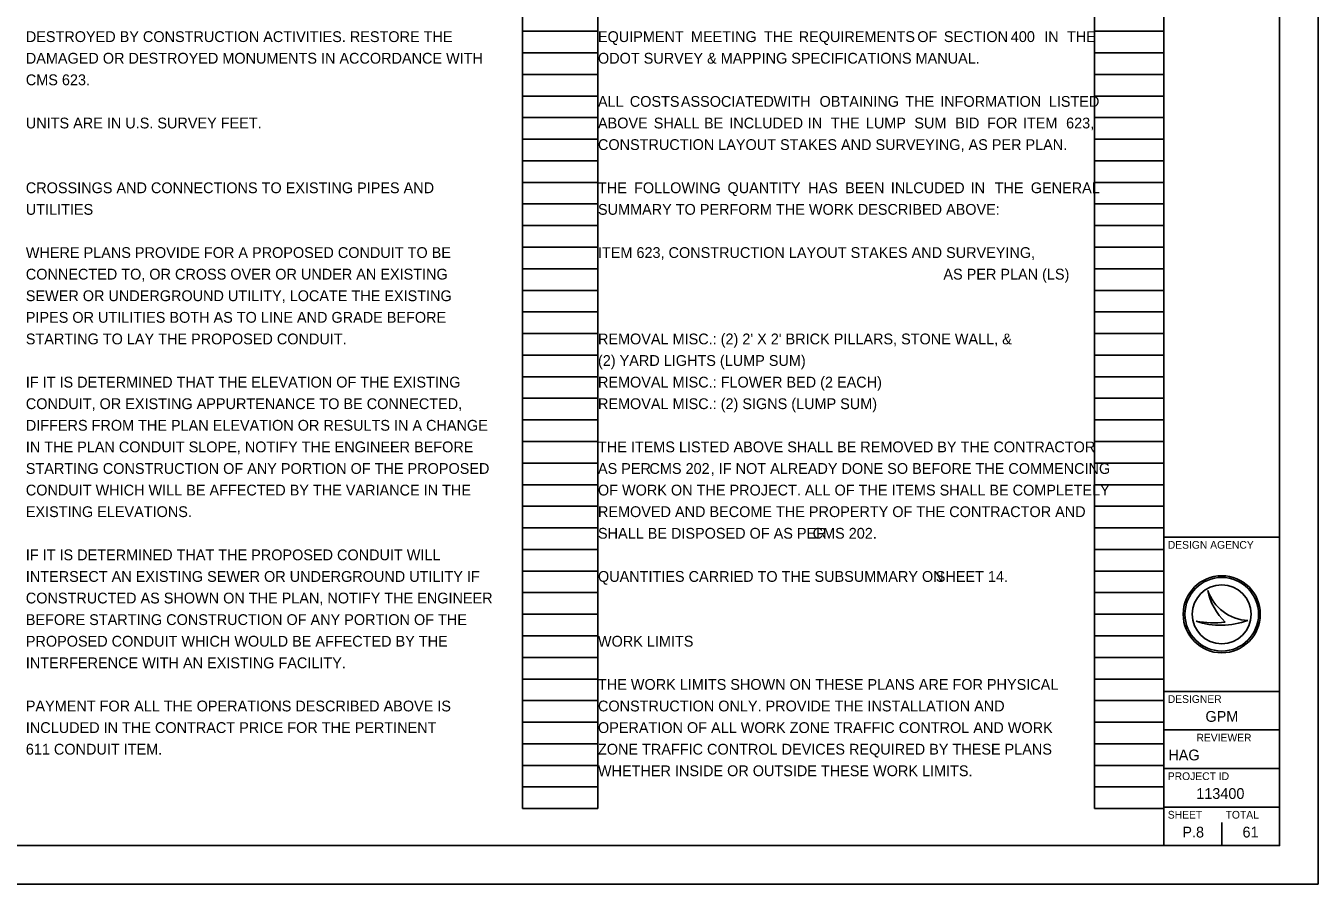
# Model space of a CAD drawing. Extents: x 0 to 34, y 0 to 22.
# Drawn here: x 17.24 to 34, y 0 to 11.13 of the extents above; entities that cross this region are included whole.
import ezdxf

# ---------------------------------------------------------------- set-up
doc = ezdxf.new("R2010")
doc.units = 0
for name, color, linetype in [('SH_Border', 7, 'Continuous'), ('SH_Cut_Line', 7, 'Continuous'), ('SH_Data', 7, 'Continuous'), ('SH_Text', 7, 'Continuous')]:
    doc.layers.add(name, color=color, linetype=linetype)

msp = doc.modelspace()

# ---------------------------------------------------------------- linework, layer by layer
at = {"layer": 'SH_Border'}
for p, q in [((32, 0.5), (32, 21.5)), ((32, 4.5), (33.5, 4.5)), ((32, 2.5), (33.5, 2.5)), ((32, 2), (33.5, 2)), ((32, 1.5), (33.5, 1.5)), ((32, 1), (33.5, 1))]:
    msp.add_line(p, q, dxfattribs=at)
msp.add_lwpolyline([(1.5, 21.5), (33.5, 21.5), (33.5, 0.5), (1.5, 0.5)], close=True, dxfattribs=at)
at = {"layer": 'SH_Cut_Line'}
msp.add_lwpolyline([(0, 0), (34, 0), (34, 22), (0, 22)], close=True, dxfattribs=at)
at = {"layer": 'SH_Data'}
for p, q in [((23.68, 0.98), (23.68, 21.14)), ((24.66, 0.98), (24.66, 21.14)), ((31.1, 0.98), (31.1, 21.14)), ((32, 0.98), (32, 21.14)), ((23.68, 11.06), (24.66, 11.06)), ((31.1, 11.06), (32, 11.06)), ((23.68, 10.78), (24.66, 10.78)), ((31.1, 10.78), (32, 10.78)), ((23.68, 10.5), (24.66, 10.5)), ((31.1, 10.5), (32, 10.5)), ((23.68, 10.22), (24.66, 10.22)), ((31.1, 10.22), (32, 10.22)), ((23.68, 9.94), (24.66, 9.94)), ((31.1, 9.94), (32, 9.94)), ((23.68, 9.66), (24.66, 9.66)), ((31.1, 9.66), (32, 9.66)), ((23.68, 9.38), (24.66, 9.38)), ((31.1, 9.38), (32, 9.38)), ((23.68, 9.1), (24.66, 9.1)), ((31.1, 9.1), (32, 9.1)), ((23.68, 8.82), (24.66, 8.82)), ((31.1, 8.82), (32, 8.82)), ((23.68, 8.54), (24.66, 8.54)), ((31.1, 8.54), (32, 8.54)), ((23.68, 8.26), (24.66, 8.26)), ((31.1, 8.26), (32, 8.26)), ((23.68, 7.98), (24.66, 7.98)), ((31.1, 7.98), (32, 7.98)), ((23.68, 7.7), (24.66, 7.7)), ((31.1, 7.7), (32, 7.7)), ((23.68, 7.42), (24.66, 7.42)), ((31.1, 7.42), (32, 7.42)), ((23.68, 7.14), (24.66, 7.14)), ((31.1, 7.14), (32, 7.14)), ((23.68, 6.86), (24.66, 6.86)), ((31.1, 6.86), (32, 6.86)), ((23.68, 6.58), (24.66, 6.58)), ((31.1, 6.58), (32, 6.58)), ((23.68, 6.3), (24.66, 6.3)), ((31.1, 6.3), (32, 6.3)), ((23.68, 6.02), (24.66, 6.02)), ((31.1, 6.02), (32, 6.02)), ((23.68, 5.74), (24.66, 5.74)), ((31.1, 5.74), (32, 5.74)), ((23.68, 5.46), (24.66, 5.46)), ((31.1, 5.46), (32, 5.46)), ((23.68, 5.18), (24.66, 5.18)), ((31.1, 5.18), (32, 5.18)), ((23.68, 4.9), (24.66, 4.9)), ((31.1, 4.9), (32, 4.9)), ((23.68, 4.62), (24.66, 4.62)), ((31.1, 4.62), (32, 4.62)), ((23.68, 4.34), (24.66, 4.34)), ((31.1, 4.34), (32, 4.34)), ((23.68, 4.06), (24.66, 4.06)), ((31.1, 4.06), (32, 4.06)), ((23.68, 3.78), (24.66, 3.78)), ((31.1, 3.78), (32, 3.78)), ((32.567, 3.81), (32.567, 3.81)), ((23.68, 3.5), (24.66, 3.5)), ((31.1, 3.5), (32, 3.5)), ((32.417, 3.41), (32.417, 3.41)), ((32.75, 3.5), (32.75, 3.5)), ((33.087, 3.419), (33.087, 3.419)), ((23.68, 3.22), (24.66, 3.22)), ((31.1, 3.22), (32, 3.22)), ((23.68, 2.94), (24.66, 2.94)), ((31.1, 2.94), (32, 2.94)), ((23.68, 2.66), (24.66, 2.66)), ((31.1, 2.66), (32, 2.66)), ((23.68, 2.38), (24.66, 2.38)), ((31.1, 2.38), (32, 2.38)), ((23.68, 2.1), (24.66, 2.1)), ((31.1, 2.1), (32, 2.1)), ((23.68, 1.82), (24.66, 1.82)), ((31.1, 1.82), (32, 1.82)), ((23.68, 1.54), (24.66, 1.54)), ((31.1, 1.54), (32, 1.54)), ((23.68, 1.26), (24.66, 1.26)), ((31.1, 1.26), (32, 1.26)), ((23.68, 0.98), (24.66, 0.98)), ((31.1, 0.98), (32, 0.98)), ((32.375, 0.675), (32.375, 0.675)), ((32.75, 0.5), (32.75, 0.8))]:
    msp.add_line(p, q, dxfattribs=at)
for radius in [0.5, 0.477, 0.477, 0.382]:
    msp.add_circle((32.75, 3.5), radius, dxfattribs=at)
for centre, radius, start, end in [((33.116, 3.998), 0.58, 198.9257, 198.9319), ((33.347, 3.97), 0.796, 191.6379, 191.6421), ((33.116, 3.998), 0.58, 198.9319, 267.1657), ((33.347, 3.97), 0.796, 191.6421, 226.0947), ((32.739, 4.37), 1.013, 251.4576, 290.0832), ((32.648, 4.654), 1.266, 259.4964, 259.4995), ((32.739, 4.37), 1.013, 251.4527, 251.4576), ((32.648, 4.654), 1.266, 259.4995, 276.6672)]:
    msp.add_arc(centre, radius, start, end, dxfattribs=at)

# ---------------------------------------------------------------- texts
for s, height, p in [('DESIGN AGENCY', 0.1, (32.05, 4.35)), ('DESIGNER', 0.1, (32.05, 2.35)), ('GPM', 0.14, (32.538, 2.105)), ('REVIEWER', 0.1, (32.422, 1.85)), ('HAG', 0.14, (32.057, 1.605)), ('PROJECT ID', 0.1, (32.05, 1.35)), ('113400', 0.14, (32.419, 1.105)), ('SHEET', 0.1, (32.05, 0.85)), ('TOTAL', 0.1, (32.8, 0.85)), ('P.8', 0.14, (32.239, 0.605)), ('61', 0.14, (33.019, 0.605))]:
    msp.add_text(s, height=height, dxfattribs=at).set_placement(p)
at = {"layer": 'SH_Text'}
for s, p in [('DESTROYED BY CONSTRUCTION ACTIVITIES. RESTORE THE', (17.24, 10.92)), ('EQUIPMENT ', (24.66, 10.92)), ('MEETING ', (25.866, 10.92)), ('REQUIREMENTS ', (27.263, 10.92)), ('OF ', (28.802, 10.92)), ('SECTION ', (29.146, 10.92)), ('400 ', (30.014, 10.92)), ('THE ', (26.813, 10.92)), ('IN ', (30.447, 10.92)), ('THE ', (30.743, 10.92)), ('DAMAGED OR DESTROYED MONUMENTS IN ACCORDANCE WITH', (17.24, 10.64)), ('ODOT SURVEY & MAPPING SPECIFICATIONS MANUAL.', (24.66, 10.64)), ('CMS 623.', (17.24, 10.36)), ('ALL ', (24.66, 10.08)), ('COSTS ', (25.073, 10.08)), ('ASSOCIATED ', (25.735, 10.08)), ('WITH ', (26.937, 10.08)), ('OBTAINING ', (27.534, 10.08)), ('THE ', (28.646, 10.08)), ('INFORMATION ', (29.098, 10.08)), ('LISTED ', (30.507, 10.08)), ('UNITS ARE IN U.S. SURVEY FEET.', (17.24, 9.8)), ('ABOVE ', (24.66, 9.8)), ('SHALL ', (25.383, 9.8)), ('BE ', (26.035, 9.8)), ('INCLUDED ', (26.363, 9.8)), ('IN ', (27.381, 9.8)), ('THE ', (27.68, 9.8)), ('LUMP ', (28.134, 9.8)), ('SUM ', (28.763, 9.8)), ('BID ', (29.294, 9.8)), ('FOR ', (29.706, 9.8)), ('ITEM ', (30.171, 9.8)), ('623, ', (30.731, 9.8)), ('CONSTRUCTION LAYOUT STAKES AND SURVEYING, AS PER PLAN.', (24.66, 9.52)), ('CROSSINGS AND CONNECTIONS TO EXISTING PIPES AND', (17.24, 8.96)), ('THE ', (24.66, 8.96)), ('FOLLOWING ', (25.128, 8.96)), ('QUANTITY ', (26.34, 8.96)), ('HAS ', (27.386, 8.96)), ('BEEN ', (27.866, 8.96)), ('INLCUDED ', (28.458, 8.96)), ('IN ', (29.493, 8.96)), ('THE ', (29.805, 8.96)), ('GENERAL ', (30.273, 8.96)), ('UTILITIES', (17.24, 8.68)), ('SUMMARY TO PERFORM THE WORK DESCRIBED ABOVE:', (24.66, 8.68)), ('WHERE PLANS PROVIDE FOR A PROPOSED CONDUIT TO BE', (17.24, 8.12)), ('ITEM 623, CONSTRUCTION LAYOUT STAKES AND SURVEYING,', (24.66, 8.12)), ('CONNECTED TO, OR CROSS OVER OR UNDER AN EXISTING', (17.24, 7.84)), ('AS PER PLAN (LS)', (29.14, 7.84)), ('SEWER OR UNDERGROUND UTILITY, LOCATE THE EXISTING', (17.24, 7.56)), ('PIPES OR UTILITIES BOTH AS TO LINE AND GRADE BEFORE', (17.24, 7.28)), ('STARTING TO LAY THE PROPOSED CONDUIT.', (17.24, 7)), ("REMOVAL MISC.: (2) 2' X 2' BRICK PILLARS, STONE WALL, &", (24.66, 7)), ('(2) YARD LIGHTS (LUMP SUM)', (24.66, 6.72)), ('IF IT IS DETERMINED THAT THE ELEVATION OF THE EXISTING', (17.24, 6.44)), ('REMOVAL MISC.: FLOWER BED (2 EACH)', (24.66, 6.44)), ('CONDUIT, OR EXISTING APPURTENANCE TO BE CONNECTED,', (17.24, 6.16)), ('REMOVAL MISC.: (2) SIGNS (LUMP SUM)', (24.66, 6.16)), ('DIFFERS FROM THE PLAN ELEVATION OR RESULTS IN A CHANGE', (17.24, 5.88)), ('IN THE PLAN CONDUIT SLOPE, NOTIFY THE ENGINEER BEFORE', (17.24, 5.6)), ('THE ITEMS LISTED ABOVE SHALL BE REMOVED BY THE CONTRACTOR', (24.66, 5.6)), ('STARTING CONSTRUCTION OF ANY PORTION OF THE PROPOSED', (17.24, 5.32)), ('AS PER ', (24.66, 5.32)), ('CMS 202', (25.328, 5.32)), (', IF NOT ALREADY DONE SO BEFORE THE COMMENCING', (26.123, 5.32)), ('CONDUIT WHICH WILL BE AFFECTED BY THE VARIANCE IN THE', (17.24, 5.04)), ('OF WORK ON THE PROJECT. ALL OF THE ITEMS SHALL BE COMPLETELY', (24.66, 5.04)), ('EXISTING ELEVATIONS.', (17.24, 4.76)), ('REMOVED AND BECOME THE PROPERTY OF THE CONTRACTOR AND', (24.66, 4.76)), ('SHALL BE DISPOSED OF AS PER ', (24.66, 4.48)), ('CMS 202.', (27.444, 4.48)), ('IF IT IS DETERMINED THAT THE PROPOSED CONDUIT WILL', (17.24, 4.2)), ('INTERSECT AN EXISTING SEWER OR UNDERGROUND UTILITY IF', (17.24, 3.92)), ('QUANTITIES CARRIED TO THE SUBSUMMARY ON ', (24.66, 3.92)), ('SHEET 14.', (29.041, 3.92)), ('CONSTRUCTED AS SHOWN ON THE PLAN, NOTIFY THE ENGINEER', (17.24, 3.64)), ('BEFORE STARTING CONSTRUCTION OF ANY PORTION OF THE', (17.24, 3.36)), ('PROPOSED CONDUIT WHICH WOULD BE AFFECTED BY THE', (17.24, 3.08)), ('WORK LIMITS', (24.66, 3.08)), ('INTERFERENCE WITH AN EXISTING FACILITY.', (17.24, 2.8)), ('THE WORK LIMITS SHOWN ON THESE PLANS ARE FOR PHYSICAL', (24.66, 2.52)), ('PAYMENT FOR ALL THE OPERATIONS DESCRIBED ABOVE IS', (17.24, 2.24)), ('CONSTRUCTION ONLY. PROVIDE THE INSTALLATION AND', (24.66, 2.24)), ('INCLUDED IN THE CONTRACT PRICE FOR THE PERTINENT', (17.24, 1.96)), ('OPERATION OF ALL WORK ZONE TRAFFIC CONTROL AND WORK', (24.66, 1.96)), ('611 CONDUIT ITEM.', (17.24, 1.68)), ('ZONE TRAFFIC CONTROL DEVICES REQUIRED BY THESE PLANS', (24.66, 1.68)), ('WHETHER INSIDE OR OUTSIDE THESE WORK LIMITS.', (24.66, 1.4))]:
    msp.add_text(s, height=0.14, dxfattribs=at).set_placement(p)

doc.saveas('drawing.dxf')
